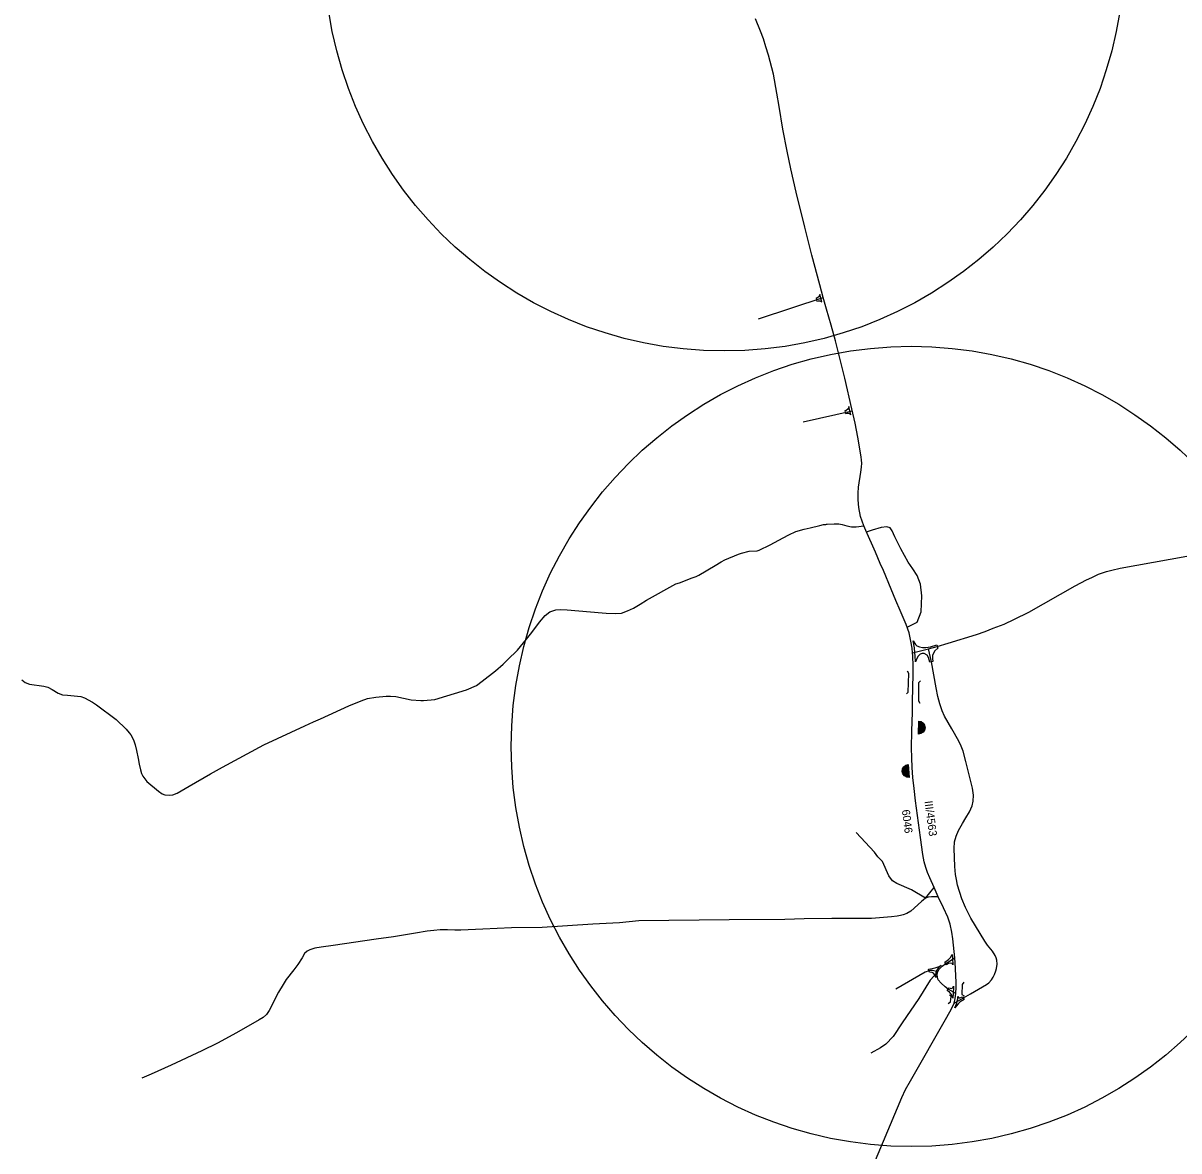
# Model space of a CAD drawing. Extents: x -546703 to -534152, y -1046534 to -1035676.
# Drawn here: x -543548 to -542103, y -1039069 to -1037660 of the extents above; entities that cross this region are included whole.
import ezdxf

# ---------------------------------------------------------------- set-up
doc = ezdxf.new("R2010")
doc.units = 0
for name, color, linetype in [('Vrstva 11', 7, 'Continuous'), ('Vrstva 22', 7, 'Continuous'), ('Vrstva 23', 7, 'Continuous'), ('Vrstva 26', 7, 'Continuous'), ('Vrstva 4', 7, 'Continuous'), ('Vrstva 7', 7, 'Continuous'), ('Vrstva 8', 7, 'Continuous')]:
    doc.layers.add(name, color=color, linetype=linetype)

msp = doc.modelspace()

# ---------------------------------------------------------------- linework, layer by layer
at = {"layer": 'Vrstva 11'}
msp.add_line((-542572.9, -1038157.6), (-542511.6, -1038143.8), dxfattribs=at)
for points in [[(-542551, -1038003.3), (-542552.3, -1037998.5), (-542552.7, -1038000), (-542553.3, -1038001.3), (-542554.5, -1038002.2), (-542556.8, -1038003.6), (-542556, -1038007), (-542554.3, -1038006.7), (-542552.3, -1038006.6), (-542550.9, -1038006.9), (-542549.7, -1038007.9)], [(-542515.1, -1038142), (-542515.9, -1038138.5), (-542516.2, -1038140.5), (-542517.2, -1038142), (-542519.1, -1038143.4), (-542520.9, -1038144.1), (-542520, -1038147.5), (-542518.2, -1038147.1), (-542516.2, -1038147.1), (-542514.8, -1038147.7), (-542513.5, -1038149.2)]]:
    msp.add_lwpolyline(points, close=True, dxfattribs=at)
for points in [[(-542629, -1038029.2), (-542587.3, -1038015.3), (-542548.1, -1038002.5)], [(-543549.3, -1038480.3), (-543545.5, -1038483.5), (-543539.8, -1038485.6), (-543522.2, -1038488.2), (-543516.9, -1038489.4), (-543511.4, -1038492.1), (-543504, -1038496.9), (-543498.5, -1038498.9), (-543492.6, -1038499.4), (-543475.7, -1038501.1), (-543471.3, -1038502.6), (-543461.2, -1038508.2), (-543456, -1038511.3), (-543431.8, -1038529.9), (-543419.2, -1038541.9), (-543415.2, -1038546.3), (-543413.1, -1038548.8), (-543410.1, -1038555.3), (-543407.8, -1038561.4), (-543406.2, -1038568.5), (-543404.3, -1038578.4), (-543402.7, -1038585.6), (-543401.3, -1038592.8), (-543399.9, -1038597.2), (-543398.1, -1038600.4), (-543393.2, -1038607.3), (-543378.6, -1038619.3), (-543374.2, -1038622.5), (-543370.8, -1038623.9), (-543365.1, -1038624.2), (-543360.7, -1038624), (-543355.4, -1038621.7), (-543340.5, -1038613), (-543313.7, -1038597.6), (-543298.6, -1038589.3), (-543247.2, -1038561.3), (-543196, -1038537.8), (-543184.9, -1038532.7), (-543176.3, -1038529), (-543140.7, -1038512.5), (-543125.4, -1038506.3), (-543117.3, -1038503.5), (-543107.2, -1038502), (-543094.1, -1038500.7), (-543088.9, -1038500.4), (-543082.1, -1038501), (-543062.9, -1038505), (-543051, -1038506.1), (-543047.5, -1038506), (-543033.3, -1038504.7), (-542993.8, -1038492.5), (-542981.4, -1038487.2), (-542974.3, -1038482), (-542957.7, -1038468.7), (-542948.1, -1038460.5), (-542942.7, -1038455), (-542930.2, -1038442.9), (-542918.9, -1038429.4), (-542912.3, -1038420.8), (-542902.7, -1038408.2), (-542895.4, -1038399.8), (-542889.5, -1038395.3), (-542882.3, -1038392.8), (-542876.8, -1038392.3), (-542868, -1038392.6), (-542824.1, -1038396.6), (-542819.3, -1038397), (-542807.2, -1038397.2), (-542800.1, -1038396.7), (-542792.6, -1038394.1), (-542784.9, -1038390.7), (-542776.7, -1038385.5), (-542769, -1038380.8), (-542732.3, -1038360), (-542727.6, -1038358.8), (-542711.7, -1038352.5), (-542706.6, -1038350.9), (-542703.4, -1038349.4), (-542683.1, -1038337.3), (-542675.6, -1038332.5), (-542670.8, -1038330.2), (-542653.7, -1038323.2), (-542650, -1038321.8), (-542640.6, -1038319.4), (-542630.4, -1038319), (-542628, -1038318.2), (-542614.3, -1038311.3), (-542598, -1038302.8), (-542590.9, -1038299), (-542582.3, -1038294.9), (-542571.7, -1038291.9), (-542564.4, -1038290), (-542552.4, -1038287.1), (-542547.8, -1038286), (-542544.6, -1038285.9)], [(-542506.8, -1038778.4), (-542508.3, -1038778.4), (-542537.2, -1038778.2), (-542571.9, -1038778.8), (-542596, -1038779.7), (-542665.7, -1038780.1), (-542778.4, -1038781.3), (-542802.5, -1038783.6), (-542835.7, -1038785.3), (-542899.2, -1038789.5), (-542937.6, -1038790), (-542973.5, -1038791.6), (-543000.9, -1038792.8), (-543008.3, -1038792.8), (-543017.7, -1038792.4), (-543026.5, -1038792.7), (-543034.7, -1038793.5), (-543042.8, -1038794.4), (-543057.6, -1038796.8), (-543085.1, -1038801.2), (-543106.5, -1038804.2), (-543160.6, -1038812), (-543175.6, -1038814), (-543183.5, -1038815.6), (-543189.4, -1038817.4), (-543193, -1038819.1), (-543196.2, -1038822.2), (-543199.2, -1038827.6), (-543204.4, -1038835.9), (-543209.4, -1038842.4), (-543219.1, -1038854.7), (-543223, -1038860.7), (-543228.7, -1038870.4), (-543240.6, -1038893.5), (-543243.9, -1038898.2), (-543248.1, -1038902.2), (-543252.9, -1038905.2), (-543281.3, -1038921.3), (-543304.9, -1038934.2), (-543324.6, -1038943.9), (-543362.9, -1038961.6), (-543387.9, -1038972.8), (-543399.4, -1038977.8)]]:
    msp.add_lwpolyline(points, dxfattribs=at)
at = {"layer": 'Vrstva 22'}
msp.add_lwpolyline([(-542486.1, -1039088.1), (-542472.8, -1039056.8), (-542449.8, -1039002.2), (-542445, -1038992.1), (-542438.9, -1038981.4), (-542393.3, -1038901.5), (-542387.5, -1038891.2), (-542384.3, -1038884.1), (-542382.9, -1038878.5), (-542382.4, -1038872.2), (-542382, -1038864.3), (-542382, -1038857.2), (-542382.1, -1038850.9), (-542382.5, -1038840.6), (-542383.3, -1038827.5), (-542385.9, -1038803.6), (-542387.1, -1038795.5), (-542389.5, -1038785.3), (-542392.3, -1038776.9), (-542397.5, -1038765.2), (-542404.4, -1038751.4), (-542409.5, -1038739.7), (-542414.9, -1038727.5), (-542417.7, -1038720.9), (-542419.7, -1038714.8), (-542421.7, -1038707.4), (-542423.4, -1038698.4), (-542426.3, -1038677.1), (-542432.6, -1038631.3), (-542434.5, -1038616), (-542435.8, -1038602.1), (-542436.7, -1038589.9), (-542437.4, -1038577.6), (-542437.8, -1038565.2), (-542437.2, -1038544.3), (-542436.5, -1038520.5), (-542436.4, -1038507.1), (-542435.6, -1038473.1), (-542435.5, -1038462.6), (-542436.1, -1038450.2), (-542436.4, -1038446.6), (-542437, -1038440.6), (-542438.3, -1038432), (-542440.7, -1038421.4), (-542444.1, -1038411.1), (-542451.7, -1038393.7), (-542457.3, -1038381.2), (-542463.1, -1038366.8), (-542472.7, -1038343.7), (-542476.7, -1038334.6), (-542482.7, -1038320.6), (-542494.7, -1038293.6), (-542497.2, -1038287.6), (-542501.2, -1038276.1), (-542503.4, -1038264.8), (-542504.3, -1038255.2), (-542504.4, -1038246.9), (-542503.9, -1038239.5), (-542501.1, -1038220.5), (-542500, -1038214.2), (-542499.9, -1038209.6), (-542500, -1038205.7), (-542500.7, -1038201.4), (-542504.9, -1038177.1), (-542508.2, -1038159.6), (-542512.2, -1038141.3), (-542520.9, -1038103.3), (-542532.6, -1038056.7), (-542538.1, -1038036.8), (-542544, -1038016.9), (-542548.1, -1038002.5), (-542552.4, -1037986.5), (-542562.3, -1037949.6), (-542571.1, -1037914.5), (-542581.7, -1037870.7), (-542588.6, -1037841.8), (-542593.2, -1037819.4), (-542598.3, -1037791.9), (-542602.9, -1037763.8), (-542605.9, -1037747.2), (-542610, -1037723.4), (-542616.3, -1037699.5), (-542619.6, -1037689.2), (-542622.6, -1037679.2), (-542626.2, -1037669.7), (-542632.5, -1037654.3)], dxfattribs=at)
at = {"layer": 'Vrstva 23'}
for points in [[(-542420.6, -1038540), (-542421.3, -1038543.1), (-542423.1, -1038545.7), (-542425.8, -1038547.4), (-542428.9, -1038547.9), (-542428.6, -1038531.7), (-542425.5, -1038532.4), (-542422.9, -1038534.2), (-542421.2, -1038536.9)], [(-542421.3, -1038540), (-542421.9, -1038542.8), (-542423.6, -1038545.2), (-542426, -1038546.8), (-542428.3, -1038547.2), (-542428, -1038532.5), (-542425.7, -1038533), (-542423.3, -1038534.6), (-542421.8, -1038537.1)], [(-542421.9, -1038540), (-542422.5, -1038542.6), (-542424, -1038544.8), (-542426.2, -1038546.2), (-542427.7, -1038546.5), (-542427.4, -1038533.2), (-542426, -1038533.5), (-542423.8, -1038535.1), (-542422.3, -1038537.3)], [(-542422.5, -1038539.9), (-542423, -1038542.3), (-542424.4, -1038544.3), (-542426.5, -1038545.7), (-542427.1, -1038545.8), (-542426.8, -1038533.9), (-542426.2, -1038534.1), (-542424.2, -1038535.5), (-542422.9, -1038537.5)], [(-542423.1, -1038539.9), (-542423.6, -1038542.1), (-542424.8, -1038543.9), (-542426.5, -1038544.9), (-542426.2, -1038534.8), (-542424.7, -1038535.9), (-542423.5, -1038537.8)], [(-542423.7, -1038539.9), (-542424.1, -1038541.8), (-542425.3, -1038543.5), (-542425.8, -1038543.8), (-542425.7, -1038535.9), (-542425.1, -1038536.3), (-542424.1, -1038538)], [(-542424.3, -1038539.9), (-542424.7, -1038541.6), (-542425.2, -1038542.3), (-542425.1, -1038537.5), (-542424.6, -1038538.2)], [(-542449.1, -1038594.6), (-542448.8, -1038591.5), (-542447.3, -1038588.7), (-542444.8, -1038586.8), (-542441.8, -1038585.9), (-542440.4, -1038602), (-542443.5, -1038601.7), (-542446.3, -1038600.1), (-542448.3, -1038597.7)], [(-542448.5, -1038594.6), (-542448.2, -1038591.7), (-542446.8, -1038589.1), (-542444.5, -1038587.3), (-542442.3, -1038586.7), (-542441, -1038601.3), (-542443.3, -1038601.1), (-542445.9, -1038599.7), (-542447.7, -1038597.4)], [(-542447.9, -1038594.5), (-542447.6, -1038591.9), (-542446.3, -1038589.5), (-542444.2, -1038587.8), (-542442.8, -1038587.4), (-542441.7, -1038600.7), (-542443.1, -1038600.5), (-542445.5, -1038599.2), (-542447.2, -1038597.1)], [(-542447.3, -1038594.5), (-542447, -1038592.1), (-542445.9, -1038589.9), (-542444, -1038588.4), (-542443.4, -1038588.2), (-542442.3, -1038600), (-542442.9, -1038599.9), (-542445.1, -1038598.7), (-542446.6, -1038596.8)], [(-542446.7, -1038594.4), (-542446.5, -1038592.2), (-542445.4, -1038590.3), (-542443.9, -1038589.1), (-542443, -1038599.2), (-542444.7, -1038598.3), (-542446.1, -1038596.5)], [(-542446.1, -1038594.4), (-542445.9, -1038592.4), (-542444.9, -1038590.7), (-542444.4, -1038590.3), (-542443.7, -1038598.1), (-542444.3, -1038597.8), (-542445.5, -1038596.3)], [(-542445.5, -1038594.3), (-542445.3, -1038592.6), (-542444.9, -1038591.8), (-542444.4, -1038596.7), (-542445, -1038596)]]:
    msp.add_lwpolyline(points, close=True, dxfattribs=at)
at = {"layer": 'Vrstva 26'}
for centre in [(-542671.7, -1037569.2), (-542437.9, -1038563.4)]:
    msp.add_circle(centre, 500, dxfattribs=at)
at = {"layer": 'Vrstva 4'}
msp.add_lwpolyline([(-542486.1, -1039088.1), (-542472.8, -1039056.8), (-542449.8, -1039002.2), (-542445, -1038992.1), (-542438.9, -1038981.4), (-542393.3, -1038901.5), (-542387.5, -1038891.2), (-542384.3, -1038884.1), (-542382.9, -1038878.5), (-542382.4, -1038872.2), (-542382, -1038864.3), (-542382, -1038857.2), (-542382.1, -1038850.9), (-542382.5, -1038840.6), (-542383.3, -1038827.5), (-542385.9, -1038803.6), (-542387.1, -1038795.5), (-542389.5, -1038785.3), (-542392.3, -1038776.9), (-542397.5, -1038765.2), (-542404.4, -1038751.4), (-542409.5, -1038739.7), (-542414.9, -1038727.5), (-542417.7, -1038720.9), (-542419.7, -1038714.8), (-542421.7, -1038707.4), (-542423.4, -1038698.4), (-542426.3, -1038677.1), (-542432.6, -1038631.3), (-542434.5, -1038616), (-542435.8, -1038602.1), (-542436.7, -1038589.9), (-542437.4, -1038577.6), (-542437.8, -1038565.2), (-542437.2, -1038544.3), (-542436.5, -1038520.5), (-542436.4, -1038507.1), (-542435.6, -1038473.1), (-542435.5, -1038462.6), (-542436.1, -1038450.2), (-542436.4, -1038446.6), (-542437, -1038440.6), (-542438.3, -1038432), (-542440.7, -1038421.4), (-542444.1, -1038411.1), (-542451.7, -1038393.7), (-542457.3, -1038381.2), (-542463.1, -1038366.8), (-542472.7, -1038343.7), (-542476.7, -1038334.6), (-542482.7, -1038320.6), (-542494.7, -1038293.6), (-542497.2, -1038287.6), (-542501.2, -1038276.1), (-542503.4, -1038264.8), (-542504.3, -1038255.2), (-542504.4, -1038246.9), (-542503.9, -1038239.5), (-542501.1, -1038220.5), (-542500, -1038214.2), (-542499.9, -1038209.6), (-542500, -1038205.7), (-542500.7, -1038201.4), (-542504.9, -1038177.1), (-542508.2, -1038159.6), (-542512.2, -1038141.3), (-542520.9, -1038103.3), (-542532.6, -1038056.7), (-542538.1, -1038036.8), (-542544, -1038016.9), (-542548.1, -1038002.5), (-542552.4, -1037986.5), (-542562.3, -1037949.6), (-542571.1, -1037914.5), (-542581.7, -1037870.7), (-542588.6, -1037841.8), (-542593.2, -1037819.4), (-542598.3, -1037791.9), (-542602.9, -1037763.8), (-542605.9, -1037747.2), (-542610, -1037723.4), (-542616.3, -1037699.5), (-542619.6, -1037689.2), (-542622.6, -1037679.2), (-542626.2, -1037669.7), (-542632.5, -1037654.3)], dxfattribs=at)
at = {"layer": 'Vrstva 7'}
msp.add_line((-542420.3, -1038753.1), (-542409.5, -1038739.7), dxfattribs=at)
for points in [[(-542544.4, -1038285.8), (-542542.9, -1038285.8), (-542534.1, -1038285.3), (-542528.4, -1038285.4), (-542524.4, -1038286), (-542518.6, -1038287.6), (-542512.5, -1038288.8), (-542506.9, -1038289), (-542497.2, -1038287.6)], [(-542443, -1038414.5), (-542430.6, -1038408), (-542425.6, -1038395.1), (-542424.7, -1038375.1), (-542426.2, -1038360.4), (-542430.4, -1038349.9), (-542435.8, -1038341.4), (-542441.9, -1038332.9), (-542450.8, -1038316.4), (-542458.5, -1038301.4), (-542461.9, -1038294.1), (-542464.2, -1038290.3), (-542468.4, -1038288.9), (-542475.5, -1038289.7), (-542486.8, -1038293.1), (-542494.2, -1038295.7)], [(-542436.4, -1038446.6), (-542416.2, -1038441.5), (-542405.5, -1038438.5), (-542391.8, -1038434.5), (-542356.2, -1038423.6), (-542345.5, -1038419.7), (-542335.4, -1038415.6), (-542321.8, -1038410.4), (-542308.7, -1038404.5), (-542290.9, -1038395.4), (-542233.1, -1038362.5), (-542219, -1038355), (-542212.3, -1038352.1), (-542203.8, -1038348.2), (-542194.1, -1038344.9), (-542187.4, -1038343.2), (-542176.8, -1038340.7), (-542093.6, -1038325.7)], [(-542384.3, -1038884.1), (-542363.7, -1038872.5), (-542343.9, -1038861), (-542341, -1038858.6), (-542337.8, -1038855.1), (-542335.7, -1038851.7), (-542334, -1038848.3), (-542332.3, -1038843.8), (-542331.6, -1038840.9), (-542330.6, -1038835.3), (-542330.8, -1038830.5), (-542331.7, -1038827.4), (-542333, -1038824.6), (-542336.5, -1038819.2), (-542342.8, -1038811.9), (-542346.1, -1038806.9), (-542363.6, -1038777.9), (-542367.7, -1038769.7), (-542370.2, -1038764.6), (-542374.6, -1038753.9), (-542380, -1038736.6), (-542381.6, -1038729.5), (-542382.5, -1038723.5), (-542383.3, -1038713.4), (-542384.3, -1038691), (-542383.7, -1038682.4), (-542381.8, -1038675.7), (-542379, -1038668.5), (-542374.1, -1038659.6), (-542369.7, -1038652.4), (-542365.1, -1038645.2), (-542361.7, -1038637.5), (-542360.4, -1038631.9), (-542360.1, -1038624.3), (-542361.6, -1038615.4), (-542369.7, -1038582.4), (-542373.2, -1038569.4), (-542375.5, -1038563), (-542378.3, -1038556.9), (-542387.1, -1038541.2), (-542396.2, -1038525.7), (-542399.3, -1038518.7), (-542402.3, -1038510.3), (-542404.7, -1038500.8), (-542406.9, -1038490), (-542412.7, -1038457.7), (-542416.2, -1038441.5)], [(-542420.3, -1038753.1), (-542437.6, -1038742.4), (-542456.1, -1038734.8), (-542461.3, -1038731.2), (-542465.8, -1038725.1), (-542473.8, -1038707.3), (-542479.5, -1038701.3), (-542483.9, -1038695.7), (-542506.9, -1038671.1)], [(-542404.4, -1038751.4), (-542412.7, -1038751.5), (-542416.6, -1038751.7), (-542420.3, -1038753.1), (-542422.9, -1038755.4), (-542425, -1038757.1), (-542438.6, -1038769.1), (-542443.6, -1038772), (-542448.2, -1038773.8), (-542451.4, -1038774.8), (-542455.7, -1038775.6), (-542462.8, -1038776.3), (-542487.7, -1038778.2), (-542500.9, -1038778.2), (-542507.3, -1038778.4)], [(-542382.4, -1038872.2), (-542391.8, -1038866.8), (-542395.7, -1038863.7), (-542400.4, -1038859.4), (-542404.2, -1038854.9), (-542405.2, -1038851.8), (-542405.5, -1038848.4), (-542404.8, -1038845), (-542402.9, -1038841.7), (-542399.3, -1038838), (-542394.9, -1038834.6), (-542383.3, -1038827.5)], [(-542404.8, -1038845), (-542414.5, -1038855.3), (-542428.6, -1038878.3), (-542449.2, -1038908.9), (-542460.4, -1038925.9), (-542469.7, -1038935.6), (-542476.2, -1038940), (-542488.3, -1038946.8)], [(-542404.8, -1038845), (-542411.4, -1038843.2), (-542413.8, -1038843.2), (-542415.9, -1038843.6), (-542420.4, -1038845.6), (-542457.3, -1038866.8)]]:
    msp.add_lwpolyline(points, dxfattribs=at)
for points in [[(-542435.4, -1038431.5), (-542432.7, -1038435.8), (-542430.8, -1038437.6), (-542427.6, -1038439.1), (-542423.7, -1038439.9), (-542419.9, -1038439.8), (-542413.9, -1038438.8), (-542406, -1038436.6), (-542404.9, -1038440.4), (-542408.6, -1038443.9), (-542410.1, -1038446.7), (-542411.3, -1038449.9), (-542411.3, -1038453.3), (-542410.8, -1038457.3), (-542414.7, -1038458.1), (-542416.5, -1038452.1), (-542418.2, -1038449.5), (-542421.6, -1038447.4), (-542424.3, -1038447.3), (-542426.7, -1038448.2), (-542429.3, -1038450.6), (-542431.1, -1038453.4), (-542432.7, -1038457.8), (-542433.1, -1038450), (-542433.4, -1038446.3), (-542434, -1038440.2)], [(-542396, -1038833), (-542391.4, -1038829.7), (-542389, -1038827.1), (-542386.8, -1038823.5), (-542386.3, -1038827.8), (-542385.8, -1038836.3), (-542386.9, -1038834.8), (-542388.7, -1038834.4), (-542391.2, -1038834.8), (-542393.7, -1038836.3)], [(-542416.5, -1038841.7), (-542414, -1038841.2), (-542408, -1038840.2), (-542405.4, -1038839.4), (-542403.2, -1038838.2), (-542400.6, -1038836.5), (-542404.5, -1038840.5), (-542406.7, -1038844.3), (-542407.5, -1038848.3), (-542407.2, -1038852.2), (-542408.6, -1038848.8), (-542410, -1038846.9), (-542411.7, -1038845.7), (-542415.3, -1038845.5)], [(-542392.9, -1038868.5), (-542390.6, -1038865.2), (-542388.1, -1038865.8), (-542386.7, -1038865.5), (-542385.8, -1038864.7), (-542385, -1038863.1), (-542385, -1038864.2), (-542385.4, -1038872), (-542385.8, -1038878), (-542386.7, -1038875.1), (-542388.1, -1038872.8), (-542390.3, -1038870.5)], [(-542379.7, -1038875.7), (-542379, -1038877.2), (-542378.3, -1038877.5), (-542377.2, -1038877.5), (-542374.1, -1038876.1), (-542372, -1038879.5), (-542376.7, -1038882.6), (-542379.4, -1038885.1), (-542383.6, -1038889.9), (-542381.4, -1038885.1), (-542379.9, -1038878.9)]]:
    msp.add_lwpolyline(points, close=True, dxfattribs=at)
at = {"layer": 'Vrstva 8'}
for points in [[(-542443.7, -1038497.8), (-542441.6, -1038495.5), (-542441.1, -1038472.4), (-542442.7, -1038469.5)], [(-542426.3, -1038481.4), (-542428.7, -1038483.8), (-542429, -1038506.3), (-542427.4, -1038509.5)], [(-542372.2, -1038858), (-542374.4, -1038860.9), (-542374.7, -1038873.2), (-542372, -1038875.2)], [(-542391.7, -1038884.6), (-542388.8, -1038882.7), (-542388.2, -1038876), (-542390.3, -1038873.8)]]:
    msp.add_lwpolyline(points, dxfattribs=at)

# ---------------------------------------------------------------- texts
at = {"layer": 'Vrstva 22'}
msp.add_text('6046', height=10, rotation=277.1751, dxfattribs=at).set_placement((-542449.7, -1038642.9))
at = {"layer": 'Vrstva 4'}
msp.add_text('III/4563', height=10, rotation=277.6736, dxfattribs=at).set_placement((-542421.4, -1038631.9))

doc.saveas('drawing.dxf')
